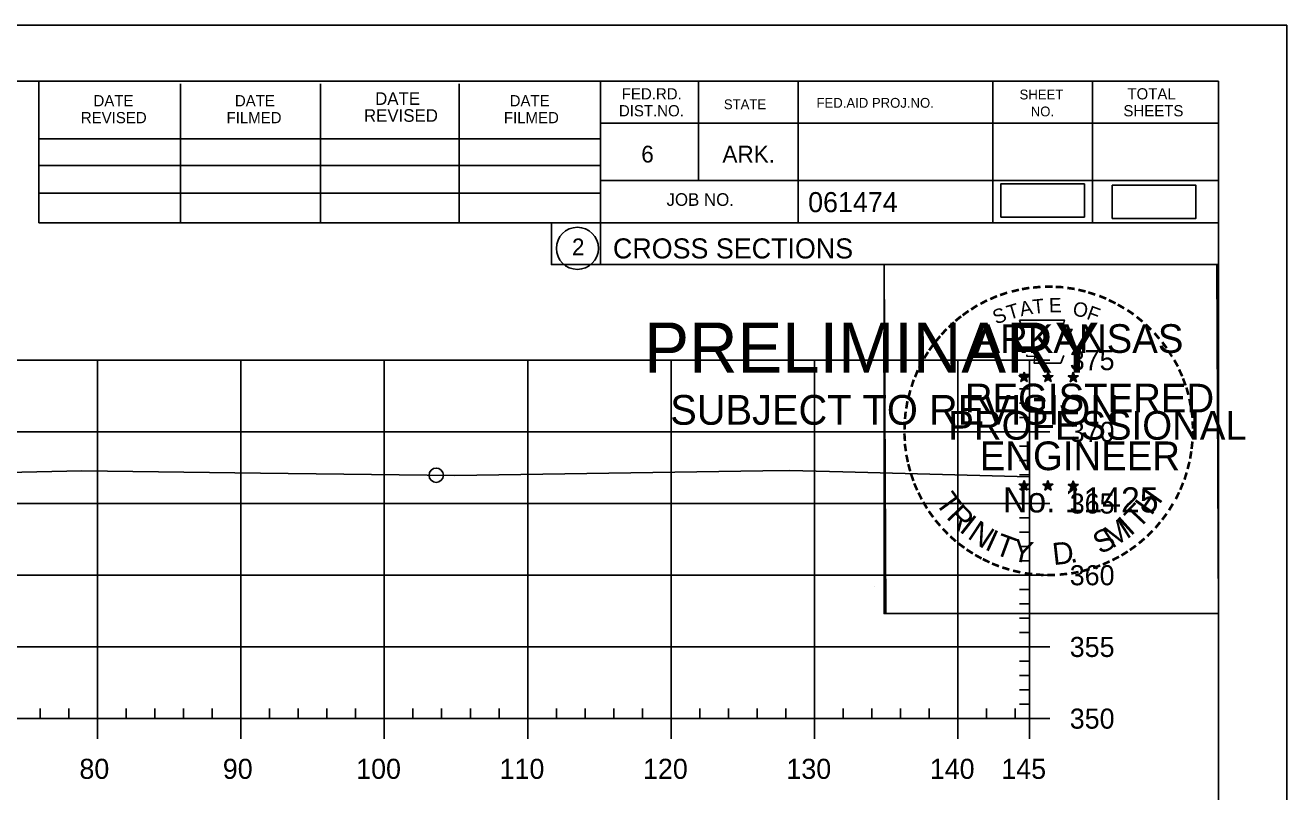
# Model space of a CAD drawing. Extents: x 1359801 to 1362404, y 372415 to 374228.
# Drawn here: x 1361894.9 to 1361982.8, y 373961.2 to 374014.6 of the extents above; entities that cross this region are included whole.
import ezdxf

# ---------------------------------------------------------------- set-up
doc = ezdxf.new("R2010")
doc.units = 0
for name, color, linetype in [('S_DRG_PT_SYM', 7, 'Continuous'), ('S_MAILBOX', 7, 'Continuous'), ('S_PRIMARY_CTL', 7, 'Continuous'), ('S_PRIMARY_CTL_ANNOT', 7, 'Continuous'), ('S_SHOULDER', 7, 'Continuous'), ('S_TELEPHONE_UTILITIES', 7, 'Continuous'), ('S_UNDERGROUND_CABLE', 7, 'Continuous'), ('S_UTL_PT_SYM', 7, 'Continuous'), ('S_WATER_UTILITIES', 7, 'Continuous')]:
    doc.layers.add(name, color=color, linetype=linetype)

msp = doc.modelspace()

# ---------------------------------------------------------------- linework, layer by layer
at = {"layer": 'S_DRG_PT_SYM'}
msp.add_lwpolyline([(1361890.396, 373983.372), (1361898.807, 373983.561), (1361911.25, 373983.395), (1361924.801, 373983.232), (1361946.276, 373983.555), (1361948.152, 373983.584), (1361951.874, 373983.484), (1361964.89, 373983.134)], dxfattribs=at)
at = {"layer": 'S_MAILBOX'}
for p, q in [((1361674.89, 373991.274), (1361964.89, 373991.274)), ((1361899.89, 373966.274), (1361899.89, 373991.274)), ((1361909.89, 373966.274), (1361909.89, 373991.274)), ((1361919.89, 373966.274), (1361919.89, 373991.274)), ((1361929.89, 373966.274), (1361929.89, 373991.274)), ((1361939.89, 373966.274), (1361939.89, 373991.274)), ((1361949.89, 373966.274), (1361949.89, 373991.274)), ((1361959.89, 373966.274), (1361959.89, 373991.274)), ((1361964.89, 373966.274), (1361964.89, 373991.274)), ((1361674.89, 373986.274), (1361964.89, 373986.274)), ((1361674.89, 373981.274), (1361964.89, 373981.274)), ((1361674.89, 373976.274), (1361964.89, 373976.274)), ((1361674.89, 373971.274), (1361964.89, 373971.274)), ((1361674.89, 373966.274), (1361964.89, 373966.274))]:
    msp.add_line(p, q, dxfattribs=at)
at = {"layer": 'S_SHOULDER'}
for p, q in [((1361649.489, 374014.628), (1361982.823, 374014.628)), ((1361954.105, 373975.478), (1361954.105, 373975.478))]:
    msp.add_line(p, q, dxfattribs=at)
for points in [[(1361649.483, 374014.628), (1361982.823, 374014.628), (1361982.823, 373801.291), (1361649.483, 373801.291)], [(1361895.81, 374010.734), (1361895.81, 374000.854), (1361931.542, 374000.854), (1361931.542, 373997.934), (1361954.742, 373997.934), (1361954.742, 373973.601), (1361978.07, 373973.601), (1361978.07, 373805.274), (1361661.89, 373805.274), (1361661.89, 374010.734)], [(1361954.742, 373997.934), (1361977.95, 373997.934), (1361978.07, 373973.601), (1361954.862, 373973.601)]]:
    msp.add_lwpolyline(points, close=True, dxfattribs=at)
msp.add_circle((1361923.508, 373983.247), 0.5, dxfattribs=at)
at = {"layer": 'S_TELEPHONE_UTILITIES'}
for p, q in [((1361964.155, 373990.189), (1361964.504, 373990.078)), ((1361964.155, 373990.189), (1361964.408, 373990.144)), ((1361964.155, 373990.189), (1361964.392, 373990.067)), ((1361964.288, 373989.781), (1361964.504, 373990.078)), ((1361964.288, 373989.781), (1361964.414, 373990.025)), ((1361964.288, 373989.781), (1361964.502, 373989.998)), ((1361964.504, 373990.443), (1361964.463, 373990.191)), ((1361964.717, 373989.781), (1361964.502, 373989.995)), ((1361964.504, 373990.078), (1361964.504, 373990.443)), ((1361964.504, 373990.443), (1361964.553, 373990.193)), ((1361964.851, 373990.189), (1361964.504, 373990.078)), ((1361964.717, 373989.781), (1361964.504, 373990.078)), ((1361964.851, 373990.189), (1361964.565, 373990.14)), ((1361964.717, 373989.781), (1361964.58, 373990.072)), ((1361964.851, 373990.189), (1361964.647, 373990.087)), ((1361965.825, 373990.189), (1361966.174, 373990.078)), ((1361965.825, 373990.189), (1361966.078, 373990.144)), ((1361965.825, 373990.189), (1361966.062, 373990.067)), ((1361965.958, 373989.781), (1361966.174, 373990.078)), ((1361965.958, 373989.781), (1361966.084, 373990.025)), ((1361965.958, 373989.781), (1361966.172, 373989.998)), ((1361966.174, 373990.443), (1361966.133, 373990.191)), ((1361966.387, 373989.781), (1361966.172, 373989.995)), ((1361966.174, 373990.078), (1361966.174, 373990.443)), ((1361966.174, 373990.443), (1361966.223, 373990.193)), ((1361966.521, 373990.189), (1361966.174, 373990.078)), ((1361966.387, 373989.781), (1361966.174, 373990.078)), ((1361966.521, 373990.189), (1361966.235, 373990.14)), ((1361966.387, 373989.781), (1361966.25, 373990.072)), ((1361966.521, 373990.189), (1361966.317, 373990.087)), ((1361967.589, 373990.177), (1361967.938, 373990.066)), ((1361967.589, 373990.177), (1361967.842, 373990.132)), ((1361967.589, 373990.177), (1361967.826, 373990.055)), ((1361967.722, 373989.769), (1361967.938, 373990.066)), ((1361967.722, 373989.769), (1361967.848, 373990.013)), ((1361967.722, 373989.769), (1361967.936, 373989.986)), ((1361967.938, 373990.431), (1361967.897, 373990.179)), ((1361968.151, 373989.769), (1361967.936, 373989.983)), ((1361967.938, 373990.066), (1361967.938, 373990.431)), ((1361967.938, 373990.431), (1361967.987, 373990.181)), ((1361968.285, 373990.177), (1361967.938, 373990.066)), ((1361968.151, 373989.769), (1361967.938, 373990.066)), ((1361968.285, 373990.177), (1361967.999, 373990.128)), ((1361968.151, 373989.769), (1361968.014, 373990.06)), ((1361968.285, 373990.177), (1361968.081, 373990.075)), ((1361964.151, 373982.616), (1361964.5, 373982.505)), ((1361964.151, 373982.616), (1361964.404, 373982.571)), ((1361964.151, 373982.616), (1361964.388, 373982.494)), ((1361964.5, 373982.87), (1361964.459, 373982.618)), ((1361964.5, 373982.505), (1361964.5, 373982.87)), ((1361964.5, 373982.87), (1361964.549, 373982.62)), ((1361964.847, 373982.616), (1361964.5, 373982.505)), ((1361964.847, 373982.616), (1361964.561, 373982.567)), ((1361964.847, 373982.616), (1361964.643, 373982.514)), ((1361965.82, 373982.616), (1361966.169, 373982.505)), ((1361965.82, 373982.616), (1361966.073, 373982.571)), ((1361965.82, 373982.616), (1361966.057, 373982.494)), ((1361966.169, 373982.87), (1361966.128, 373982.618)), ((1361966.169, 373982.505), (1361966.169, 373982.87)), ((1361966.169, 373982.87), (1361966.218, 373982.62)), ((1361966.516, 373982.616), (1361966.169, 373982.505)), ((1361966.516, 373982.616), (1361966.23, 373982.567)), ((1361966.516, 373982.616), (1361966.312, 373982.514)), ((1361967.587, 373982.606), (1361967.936, 373982.495)), ((1361967.587, 373982.606), (1361967.84, 373982.561)), ((1361967.587, 373982.606), (1361967.824, 373982.484)), ((1361967.936, 373982.86), (1361967.895, 373982.608)), ((1361967.936, 373982.495), (1361967.936, 373982.86)), ((1361967.936, 373982.86), (1361967.985, 373982.61)), ((1361968.283, 373982.606), (1361967.936, 373982.495)), ((1361968.283, 373982.606), (1361967.997, 373982.557)), ((1361968.283, 373982.606), (1361968.079, 373982.504)), ((1361964.284, 373982.208), (1361964.5, 373982.505)), ((1361964.284, 373982.208), (1361964.41, 373982.452)), ((1361964.284, 373982.208), (1361964.498, 373982.425)), ((1361964.713, 373982.208), (1361964.498, 373982.422)), ((1361964.713, 373982.208), (1361964.5, 373982.505)), ((1361964.713, 373982.208), (1361964.576, 373982.499)), ((1361965.953, 373982.208), (1361966.169, 373982.505)), ((1361965.953, 373982.208), (1361966.079, 373982.452)), ((1361965.953, 373982.208), (1361966.167, 373982.425)), ((1361966.382, 373982.208), (1361966.167, 373982.422)), ((1361966.382, 373982.208), (1361966.169, 373982.505)), ((1361966.382, 373982.208), (1361966.245, 373982.499)), ((1361967.72, 373982.198), (1361967.936, 373982.495)), ((1361967.72, 373982.198), (1361967.846, 373982.442)), ((1361967.72, 373982.198), (1361967.934, 373982.415)), ((1361968.149, 373982.198), (1361967.934, 373982.412)), ((1361968.149, 373982.198), (1361967.936, 373982.495)), ((1361968.149, 373982.198), (1361968.012, 373982.489))]:
    msp.add_line(p, q, dxfattribs=at)
for points in [[(1361964.196, 373994.067), (1361964.465, 373993.24)], [(1361967.707, 373993.145), (1361967.849, 373993.429), (1361967.164, 373993.405), (1361967.312, 373994.067), (1361964.196, 373994.067)], [(1361964.688, 373991.644), (1361964.688, 373991.557), (1361965.251, 373991.538), (1361965.197, 373991.065), (1361967.067, 373991.065), (1361967.268, 373991.601)], [(1361964.504, 373990.443), (1361964.717, 373989.781), (1361964.155, 373990.189), (1361964.851, 373990.189), (1361964.288, 373989.781), (1361964.504, 373990.443)], [(1361966.174, 373990.443), (1361966.387, 373989.781), (1361965.825, 373990.189), (1361966.521, 373990.189), (1361965.958, 373989.781), (1361966.174, 373990.443)], [(1361967.938, 373990.431), (1361968.151, 373989.769), (1361967.589, 373990.177), (1361968.285, 373990.177), (1361967.722, 373989.769), (1361967.938, 373990.431)], [(1361964.5, 373982.87), (1361964.713, 373982.208), (1361964.151, 373982.616), (1361964.847, 373982.616), (1361964.284, 373982.208), (1361964.5, 373982.87)], [(1361966.169, 373982.87), (1361966.382, 373982.208), (1361965.82, 373982.616), (1361966.516, 373982.616), (1361965.953, 373982.208), (1361966.169, 373982.87)], [(1361967.936, 373982.86), (1361968.149, 373982.198), (1361967.587, 373982.606), (1361968.283, 373982.606), (1361967.72, 373982.198), (1361967.936, 373982.86)]]:
    msp.add_lwpolyline(points, dxfattribs=at)
for centre, radius in [((1361964.503, 373990.077), 0.172), ((1361964.503, 373990.077), 0.145), ((1361964.503, 373990.077), 0.116), ((1361964.503, 373990.077), 0.0991), ((1361964.503, 373990.077), 0.0747), ((1361964.503, 373990.077), 0.0495), ((1361964.503, 373990.077), 0.0296), ((1361966.173, 373990.077), 0.172), ((1361966.173, 373990.077), 0.145), ((1361966.173, 373990.077), 0.116), ((1361966.173, 373990.077), 0.0991), ((1361966.173, 373990.077), 0.0747), ((1361966.173, 373990.077), 0.0495), ((1361966.173, 373990.077), 0.0296), ((1361967.937, 373990.065), 0.172), ((1361967.937, 373990.065), 0.145), ((1361967.937, 373990.065), 0.116), ((1361967.937, 373990.065), 0.0991), ((1361967.937, 373990.065), 0.0747), ((1361967.937, 373990.065), 0.0495), ((1361967.937, 373990.065), 0.0296), ((1361964.499, 373982.504), 0.172), ((1361964.499, 373982.504), 0.145), ((1361964.499, 373982.504), 0.116), ((1361964.499, 373982.504), 0.0991), ((1361966.168, 373982.504), 0.172), ((1361966.168, 373982.504), 0.145), ((1361966.168, 373982.504), 0.116), ((1361966.168, 373982.504), 0.0991), ((1361967.935, 373982.494), 0.172), ((1361967.935, 373982.494), 0.145), ((1361967.935, 373982.494), 0.116), ((1361967.935, 373982.494), 0.0991), ((1361964.499, 373982.504), 0.0747), ((1361964.499, 373982.504), 0.0495), ((1361964.499, 373982.504), 0.0296), ((1361966.168, 373982.504), 0.0747), ((1361966.168, 373982.504), 0.0495), ((1361966.168, 373982.504), 0.0296), ((1361967.935, 373982.494), 0.0747), ((1361967.935, 373982.494), 0.0495), ((1361967.935, 373982.494), 0.0296)]:
    msp.add_circle(centre, radius, dxfattribs=at)
at = {"layer": 'S_UNDERGROUND_CABLE'}
for points in [[(1361962.88, 374001.253), (1361968.713, 374001.253), (1361968.713, 374003.564), (1361962.88, 374003.564)], [(1361970.649, 374001.16), (1361976.482, 374001.16), (1361976.482, 374003.47), (1361970.649, 374003.47)]]:
    msp.add_lwpolyline(points, close=True, dxfattribs=at)
at = {"layer": 'S_UTL_PT_SYM'}
for p, q in [((1361661.89, 374010.734), (1361978.07, 374010.734)), ((1361895.81, 374000.854), (1361895.81, 374010.734)), ((1361905.67, 374000.854), (1361905.67, 374010.534)), ((1361915.43, 374000.854), (1361915.43, 374010.534)), ((1361925.11, 374000.854), (1361925.11, 374010.534)), ((1361934.97, 374010.734), (1361934.97, 373997.934)), ((1361941.81, 374010.734), (1361941.81, 374003.794)), ((1361948.75, 374010.734), (1361948.75, 374000.854)), ((1361962.33, 374010.734), (1361962.33, 374000.854)), ((1361969.27, 374010.734), (1361969.27, 374000.854)), ((1361978.07, 373805.274), (1361978.07, 374010.734)), ((1361978.07, 374007.794), (1361934.97, 374007.794)), ((1361978.07, 374007.814), (1361978.07, 374007.814)), ((1361895.81, 374006.714), (1361934.97, 374006.714)), ((1361895.81, 374004.854), (1361934.97, 374004.854)), ((1361978.07, 374003.794), (1361934.97, 374003.794)), ((1361937.93, 374003.794), (1361978.07, 374003.794)), ((1361895.81, 374000.854), (1361895.81, 374002.914)), ((1361895.81, 374002.914), (1361934.97, 374002.914)), ((1361978.07, 374000.854), (1361895.81, 374000.854)), ((1361934.97, 373997.934), (1361978.07, 373997.934))]:
    msp.add_line(p, q, dxfattribs=at)
msp.add_circle((1361933.357, 373999.069), 1.467, dxfattribs=at)
at = {"layer": 'S_WATER_UTILITIES'}
for p, q in [((1361964.89, 373966.274), (1361964.89, 373991.274)), ((1361966.29, 373991.274), (1361964.89, 373991.274)), ((1361964.89, 373990.274), (1361964.19, 373990.274)), ((1361964.89, 373989.274), (1361964.19, 373989.274)), ((1361964.89, 373988.274), (1361964.19, 373988.274)), ((1361964.89, 373987.274), (1361964.19, 373987.274)), ((1361966.29, 373986.274), (1361964.89, 373986.274)), ((1361964.89, 373985.274), (1361964.19, 373985.274)), ((1361964.89, 373984.274), (1361964.19, 373984.274)), ((1361964.89, 373983.274), (1361964.19, 373983.274)), ((1361964.89, 373982.274), (1361964.19, 373982.274)), ((1361966.29, 373981.274), (1361964.89, 373981.274)), ((1361964.89, 373980.274), (1361964.19, 373980.274)), ((1361964.89, 373979.274), (1361964.19, 373979.274)), ((1361964.89, 373978.274), (1361964.19, 373978.274)), ((1361964.89, 373977.274), (1361964.19, 373977.274)), ((1361966.29, 373976.274), (1361964.89, 373976.274)), ((1361964.89, 373975.274), (1361964.19, 373975.274)), ((1361964.89, 373974.274), (1361964.19, 373974.274)), ((1361964.89, 373973.274), (1361964.19, 373973.274)), ((1361964.89, 373972.274), (1361964.19, 373972.274)), ((1361966.29, 373971.274), (1361964.89, 373971.274)), ((1361964.89, 373970.274), (1361964.19, 373970.274)), ((1361964.89, 373969.274), (1361964.19, 373969.274)), ((1361964.89, 373968.274), (1361964.19, 373968.274)), ((1361895.89, 373966.274), (1361895.89, 373966.974)), ((1361897.89, 373966.274), (1361897.89, 373966.974)), ((1361901.89, 373966.274), (1361901.89, 373966.974)), ((1361903.89, 373966.274), (1361903.89, 373966.974)), ((1361905.89, 373966.274), (1361905.89, 373966.974)), ((1361907.89, 373966.274), (1361907.89, 373966.974)), ((1361911.89, 373966.274), (1361911.89, 373966.974)), ((1361913.89, 373966.274), (1361913.89, 373966.974)), ((1361915.89, 373966.274), (1361915.89, 373966.974)), ((1361917.89, 373966.274), (1361917.89, 373966.974)), ((1361921.89, 373966.274), (1361921.89, 373966.974)), ((1361923.89, 373966.274), (1361923.89, 373966.974)), ((1361925.89, 373966.274), (1361925.89, 373966.974)), ((1361927.89, 373966.274), (1361927.89, 373966.974)), ((1361931.89, 373966.274), (1361931.89, 373966.974)), ((1361933.89, 373966.274), (1361933.89, 373966.974)), ((1361935.89, 373966.274), (1361935.89, 373966.974)), ((1361937.89, 373966.274), (1361937.89, 373966.974)), ((1361941.89, 373966.274), (1361941.89, 373966.974)), ((1361943.89, 373966.274), (1361943.89, 373966.974)), ((1361945.89, 373966.274), (1361945.89, 373966.974)), ((1361947.89, 373966.274), (1361947.89, 373966.974)), ((1361951.89, 373966.274), (1361951.89, 373966.974)), ((1361953.89, 373966.274), (1361953.89, 373966.974)), ((1361955.89, 373966.274), (1361955.89, 373966.974)), ((1361957.89, 373966.274), (1361957.89, 373966.974)), ((1361961.89, 373966.274), (1361961.89, 373966.974)), ((1361963.89, 373966.274), (1361963.89, 373966.974)), ((1361964.89, 373967.274), (1361964.19, 373967.274)), ((1361674.89, 373966.274), (1361964.89, 373966.274)), ((1361899.89, 373964.874), (1361899.89, 373966.274)), ((1361909.89, 373964.874), (1361909.89, 373966.274)), ((1361919.89, 373964.874), (1361919.89, 373966.274)), ((1361929.89, 373964.874), (1361929.89, 373966.274)), ((1361939.89, 373964.874), (1361939.89, 373966.274)), ((1361949.89, 373964.874), (1361949.89, 373966.274)), ((1361959.89, 373964.874), (1361959.89, 373966.274)), ((1361964.89, 373964.874), (1361964.89, 373966.274)), ((1361966.29, 373966.274), (1361964.89, 373966.274))]:
    msp.add_line(p, q, dxfattribs=at)

# ---------------------------------------------------------------- texts
at = {"layer": 'S_PRIMARY_CTL'}
for s, p in [('375', (1361967.69, 373990.574)), ('370', (1361967.69, 373985.574)), ('365', (1361967.69, 373980.574)), ('360', (1361967.69, 373975.574)), ('355', (1361967.69, 373970.574)), ('350', (1361967.69, 373965.574)), ('80', (1361898.629, 373962.074)), ('90', (1361908.629, 373962.074)), ('100', (1361917.929, 373962.074)), ('110', (1361927.929, 373962.074)), ('120', (1361937.929, 373962.074)), ('130', (1361947.929, 373962.074)), ('140', (1361957.929, 373962.074)), ('145', (1361962.916, 373962.074))]:
    msp.add_text(s, height=1.4, dxfattribs=at).set_placement(p)
at = {"layer": 'S_PRIMARY_CTL_ANNOT'}
for s, height, p in [('PRELIMINARY', 3.5, (1361938.021, 373990.397)), ('DWB', 0.01, (1361938.768, 373992.246)), ('SUBJECT TO REVISION', 2.07511, (1361939.83, 373986.768))]:
    msp.add_text(s, height=height, rotation=360, dxfattribs=at).set_placement(p)
at = {"layer": 'S_TELEPHONE_UTILITIES'}
for s, height, rotation, p in [('-', 1.6, 24.30721, (1361962.31, 373994.925)), ('-', 1.6, 19.17608, (1361962.944, 373995.194)), ('-', 1.6, 13.63015, (1361963.694, 373995.435)), ('-', 1.6, 10.21935, (1361964.372, 373995.597)), ('-', 1.6, 5.89682, (1361965.101, 373995.707)), ('-', 1.6, 0.18623, (1361965.873, 373995.779)), ('-', 1.6, 357.74304, (1361966.596, 373995.766)), ('-', 1.6, 352.16172, (1361967.34, 373995.71)), ('-', 1.6, 347.20489, (1361968.059, 373995.596)), ('-', 1.6, 342.3362, (1361968.694, 373995.441)), ('-', 1.6, 337.85509, (1361969.429, 373995.218)), ('-', 1.6, 34.06357, (1361961.08, 373994.238)), ('-', 1.6, 28.79182, (1361961.677, 373994.608)), ('S', 1, 21.59401, (1361962.551, 373993.745)), ('T', 1, 16.4036, (1361963.465, 373994.076)), ('A', 1, 11.21318, (1361964.291, 373994.327)), ('T', 1, 6.02276, (1361965.14, 373994.493)), ('E', 1, 0.83234, (1361966.245, 373994.603)), ('O', 1, 350.4515, (1361967.849, 373994.393)), ('F', 1, 340.07066, (1361968.803, 373994.165)), ('-', 1.6, 334.12109, (1361970.06, 373994.947)), ('-', 1.6, 329.64089, (1361970.639, 373994.664)), ('-', 1.6, 38.95066, (1361960.026, 373993.465)), ('-', 1.6, 36.23174, (1361960.502, 373993.843)), ('-', 1.6, 325.86266, (1361971.282, 373994.303)), ('-', 1.6, 320.52971, (1361971.892, 373993.877)), ('-', 1.6, 48.42305, (1361959.145, 373992.57)), ('-', 1.6, 42.96224, (1361959.593, 373993.048)), ('ARKANSAS', 2, 360, (1361961.049, 373991.779)), ('-', 1.6, 315.57859, (1361972.491, 373993.389)), ('-', 1.6, 309.87973, (1361973.06, 373992.839)), ('-', 1.6, 54.23247, (1361958.329, 373991.517)), ('-', 1.6, 50.61417, (1361958.742, 373992.084)), ('-', 1.6, 306.65218, (1361973.585, 373992.237)), ('-', 1.6, 58.07063, (1361958.004, 373990.99)), ('-', 1.4, 303.67529, (1361974.071, 373991.669)), ('-', 1.6, 67.77427, (1361957.432, 373989.765)), ('-', 1.6, 62.87135, (1361957.691, 373990.376)), ('-', 1.6, 299.66835, (1361974.39, 373991.062)), ('-', 1.6, 294.66279, (1361974.714, 373990.45)), ('-', 1.6, 72.39447, (1361957.213, 373989.135)), ('REGISTERED', 2, 360, (1361960.371, 373987.63)), ('DWB', 0.01, 360, (1361964.491, 373990.073)), ('DWB', 0.01, 360, (1361966.161, 373990.073)), ('DWB', 0.01, 360, (1361967.925, 373990.062)), ('-', 1.6, 290.57283, (1361974.971, 373989.873)), ('-', 1.6, 75.46096, (1361957.016, 373988.421)), ('-', 1.6, 285.12326, (1361975.205, 373989.293)), ('-', 1.6, 81.20126, (1361956.884, 373987.708)), ('-', 1.6, 280.54934, (1361975.405, 373988.551)), ('-', 1.6, 85.18634, (1361956.808, 373987.017)), ('PROFESSIONAL', 2, 360, (1361959.223, 373985.726)), ('-', 1.6, 276.59616, (1361975.567, 373987.783)), ('-', 1.6, 274.33011, (1361975.627, 373987.061)), ('-', 1.6, 94.19588, (1361956.818, 373985.591)), ('-', 1.6, 89.06224, (1361956.783, 373986.316)), ('-', 1.6, 269.94067, (1361975.661, 373986.429)), ('-', 1.6, 98.94793, (1361956.89, 373984.924)), ('ENGINEER', 2, 360, (1361961.41, 373983.601)), ('-', 1.6, 263.5172, (1361975.642, 373985.763)), ('-', 1.6, 101.71495, (1361957.025, 373984.191)), ('-', 1.6, 260.99529, (1361975.571, 373985.109)), ('-', 1.6, 105.45785, (1361957.187, 373983.596)), ('-', 1.6, 255.7626, (1361975.461, 373984.431)), ('-', 1.6, 109.08742, (1361957.402, 373982.965)), ('-', 1.6, 114.06432, (1361957.656, 373982.369)), ('-', 1.6, 247.88866, (1361975.057, 373983.038)), ('-', 1.6, 252.86809, (1361975.28, 373983.711)), ('-', 1.6, 115.72885, (1361957.961, 373981.751)), ('T', 1.54, 306.04056, (1361958.26, 373981.343)), ('No. 11425', 1.757, 360, (1361963.038, 373980.65)), ('DWB', 0.01, 360, (1361964.487, 373982.5)), ('DWB', 0.01, 360, (1361966.156, 373982.5)), ('DWB', 0.01, 360, (1361967.923, 373982.49)), ('H', 1.54, 54.60883, (1361973.38, 373980.378)), ('-', 1.6, 244.61971, (1361974.795, 373982.409)), ('-', 1.6, 120.44712, (1361958.318, 373981.165)), ('R', 1.54, 314.00497, (1361959.022, 373980.295)), ('T', 1.54, 46.64442, (1361972.49, 373979.436)), ('-', 1.6, 239.07125, (1361974.401, 373981.657)), ('-', 1.6, 125.89344, (1361958.721, 373980.604)), ('-', 1.6, 130.71812, (1361959.183, 373980.052)), ('I', 1.54, 321.96938, (1361959.923, 373979.363)), ('N', 1.54, 326.50021, (1361960.49, 373978.892)), ('M', 1.54, 32.65632, (1361970.645, 373978.111)), ('I', 1.54, 42.11359, (1361971.929, 373978.958)), ('-', 1.6, 231.25377, (1361973.569, 373980.438)), ('-', 1.6, 233.84524, (1361973.999, 373981.004)), ('-', 1.6, 134.22381, (1361959.7, 373979.507)), ('I', 1.54, 335.36034, (1361961.698, 373978.106)), ('T', 1.54, 339.89117, (1361962.359, 373977.778)), ('S', 1.54, 26.9312, (1361969.806, 373977.705)), ('-', 1.6, 225.76533, (1361973.09, 373979.874)), ('-', 1.6, 138.93382, (1361960.225, 373979.043)), ('-', 1.6, 144.64634, (1361960.781, 373978.637)), ('Y', 1.54, 347.85558, (1361963.576, 373977.333)), ('D', 1.54, 6.39691, (1361966.561, 373976.974)), ('-', 1.6, 215.73633, (1361972.019, 373978.893)), ('-', 1.6, 221.08509, (1361972.568, 373979.365)), ('-', 1.6, 148.08978, (1361961.342, 373978.266)), ('-', 1.6, 151.57039, (1361961.921, 373977.941)), ('-', 1.6, 154.60019, (1361962.443, 373977.694)), ('.', 1.54, 13.76417, (1361967.753, 373977.102)), ('-', 1.6, 204.25161, (1361970.303, 373977.841)), ('-', 1.6, 207.35684, (1361970.927, 373978.16)), ('-', 1.6, 212.24909, (1361971.485, 373978.506)), ('-', 1.6, 158.56121, (1361963.067, 373977.44)), ('-', 1.6, 162.79826, (1361963.754, 373977.227)), ('-', 1.6, 167.55551, (1361964.469, 373977.063)), ('-', 1.6, 173.11546, (1361965.241, 373976.953)), ('-', 1.6, 185.81666, (1361967.542, 373976.995)), ('-', 1.6, 191.28576, (1361968.278, 373977.127)), ('-', 1.6, 195.47429, (1361969.007, 373977.326)), ('-', 1.6, 200.71842, (1361969.684, 373977.568)), ('-', 1.6, 176.51827, (1361965.989, 373976.9)), ('-', 1.6, 181.59176, (1361966.733, 373976.919))]:
    msp.add_text(s, height=height, rotation=rotation, dxfattribs=at).set_placement(p)
at = {"layer": 'S_UTL_PT_SYM'}
for s, height, p in [('DATE', 0.8792, (1361919.25, 374009.074)), ('FED.RD.', 0.7819, (1361936.45, 374009.454)), ('SHEET', 0.684, (1361964.19, 374009.454)), ('TOTAL', 0.7819, (1361971.71, 374009.454)), ('DATE', 0.7819, (1361899.61, 374008.974)), ('DATE', 0.7819, (1361909.47, 374008.974)), ('DATE', 0.7819, (1361928.63, 374008.974)), ('DIST.NO.', 0.7819, (1361936.25, 374008.274)), ('STATE', 0.684, (1361943.57, 374008.774)), ('FED.AID PROJ.NO.', 0.684, (1361950.03, 374008.874)), ('SHEETS', 0.7819, (1361971.43, 374008.274)), ('REVISED', 0.7819, (1361898.73, 374007.794)), ('FILMED', 0.7819, (1361908.89, 374007.794)), ('REVISED', 0.8792, (1361918.47, 374007.894)), ('FILMED', 0.7819, (1361928.23, 374007.794)), ('NO.', 0.684, (1361964.97, 374008.274)), ('6', 1.172, (1361937.81, 374005.054)), ('ARK.', 1.1723, (1361943.47, 374005.054)), ('JOB NO.', 0.8792, (1361939.57, 374002.034)), ('061474', 1.4, (1361949.446, 374001.593)), ('2', 1.172, (1361932.974, 373998.583)), ('CROSS SECTIONS', 1.4, (1361935.834, 373998.364))]:
    msp.add_text(s, height=height, rotation=360, dxfattribs=at).set_placement(p)

doc.saveas('drawing.dxf')
